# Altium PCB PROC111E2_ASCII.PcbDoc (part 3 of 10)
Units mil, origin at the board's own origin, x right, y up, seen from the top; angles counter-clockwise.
Board outline 7700 x 2300 mil, 6 copper layers (Top Layer, GND 1, SIG 1, SIG 2, GND 2, Bottom Layer), stack 78.711 mil thick; 767 components, 596 nets, 2755 pads, 1578 vias.
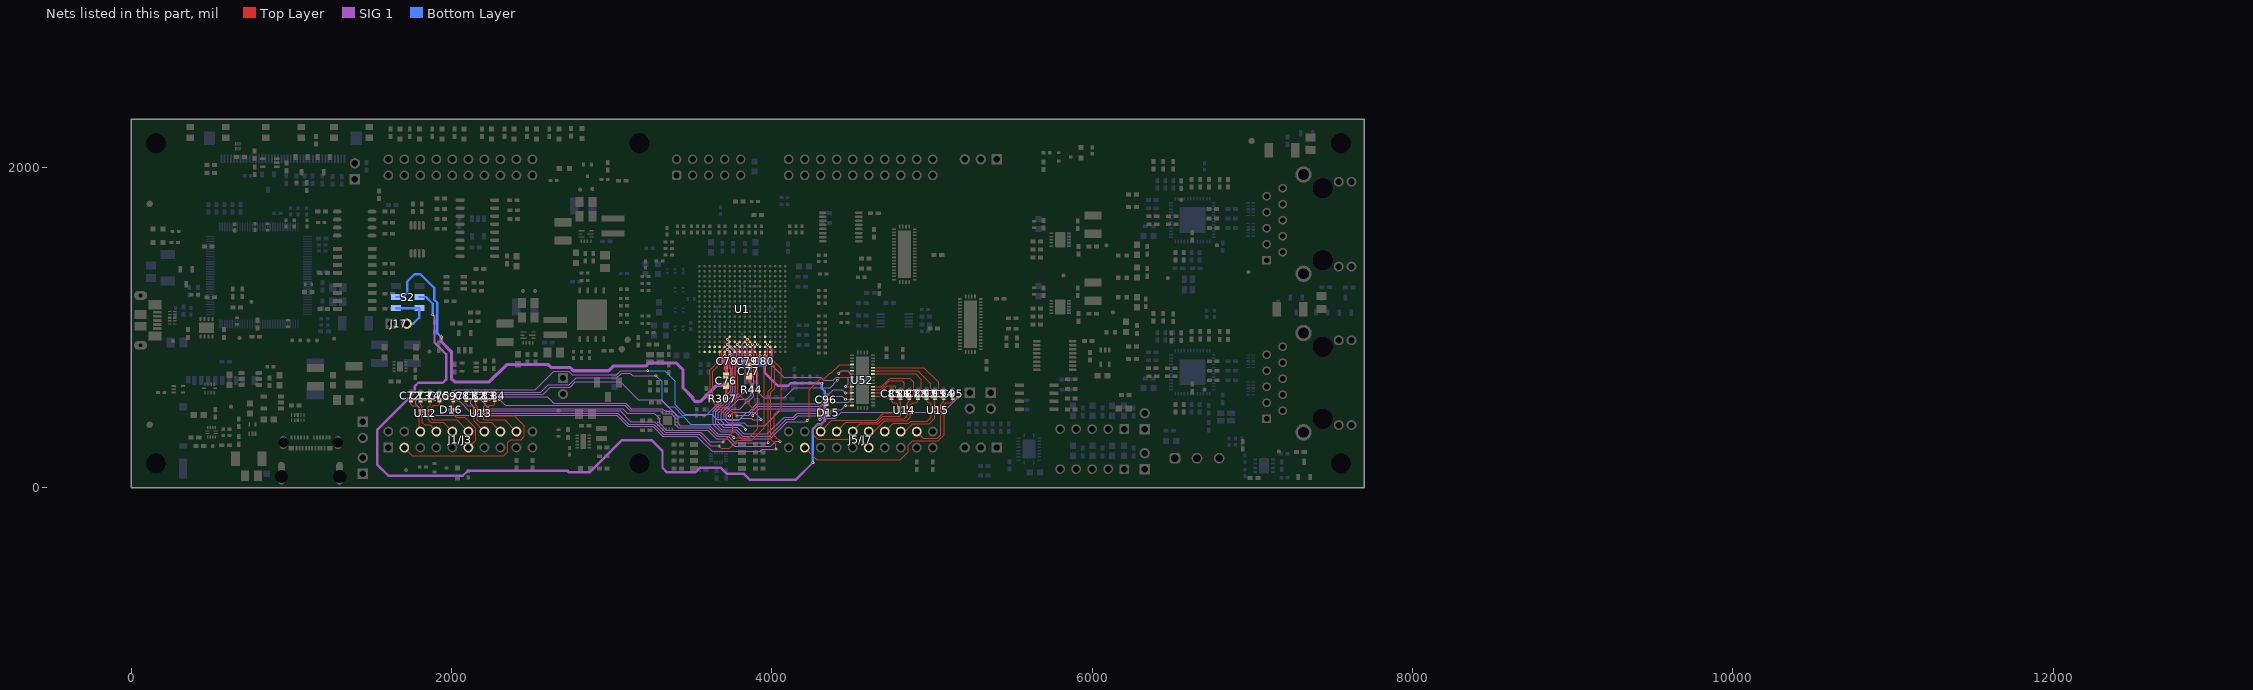
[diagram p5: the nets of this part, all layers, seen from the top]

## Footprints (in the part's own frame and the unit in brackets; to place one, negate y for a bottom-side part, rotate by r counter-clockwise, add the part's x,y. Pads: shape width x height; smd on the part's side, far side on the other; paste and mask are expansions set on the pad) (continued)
PDT0128A [mm] "Thin QFP, 128-Leads, Body 14x14mm, Pitch 0.4mm"
  oval 1.4x0.2 smd: 1(-7.7,6.2) 2(-7.7,5.8) 3(-7.7,5.4) 4(-7.7,5) 5(-7.7,4.6) 6(-7.7,4.2) 7(-7.7,3.8) 8(-7.7,3.4) 9(-7.7,3) 10(-7.7,2.6) 11(-7.7,2.2) 12(-7.7,1.8) 13(-7.7,1.4) 14(-7.7,1) 15(-7.7,0.6) 16(-7.7,0.2) 17(-7.7,-0.2) 18(-7.7,-0.6) 19(-7.7,-1) 20(-7.7,-1.4) 21(-7.7,-1.8) 22(-7.7,-2.2) 23(-7.7,-2.6) 24(-7.7,-3) 25(-7.7,-3.4) 26(-7.7,-3.8) 27(-7.7,-4.2) 28(-7.7,-4.6) 29(-7.7,-5) 30(-7.7,-5.4) 31(-7.7,-5.8) 32(-7.7,-6.2) 65(7.7,-6.2) 66(7.7,-5.8) 67(7.7,-5.4) 68(7.7,-5) 69(7.7,-4.6) 70(7.7,-4.2) 71(7.7,-3.8) 72(7.7,-3.4) 73(7.7,-3) 74(7.7,-2.6) 75(7.7,-2.2) 76(7.7,-1.8) 77(7.7,-1.4) 78(7.7,-1) 79(7.7,-0.6) 80(7.7,-0.2) 81(7.7,0.2) 82(7.7,0.6) 83(7.7,1) 84(7.7,1.4) 85(7.7,1.8) 86(7.7,2.2) 87(7.7,2.6) 88(7.7,3) 89(7.7,3.4) 90(7.7,3.8) 91(7.7,4.2) 92(7.7,4.6) 93(7.7,5) 94(7.7,5.4) 95(7.7,5.8) 96(7.7,6.2)
  oval 0.2x1.4 smd: 33(-6.2,-7.7) 34(-5.8,-7.7) 35(-5.4,-7.7) 36(-5,-7.7) 37(-4.6,-7.7) 38(-4.2,-7.7) 39(-3.8,-7.7) 40(-3.4,-7.7) 41(-3,-7.7) 42(-2.6,-7.7) 43(-2.2,-7.7) 44(-1.8,-7.7) 45(-1.4,-7.7) 46(-1,-7.7) 47(-0.6,-7.7) 48(-0.2,-7.7) 49(0.2,-7.7) 50(0.6,-7.7) 51(1,-7.7) 52(1.4,-7.7) 53(1.8,-7.7) 54(2.2,-7.7) 55(2.6,-7.7) 56(3,-7.7) 57(3.4,-7.7) 58(3.8,-7.7) 59(4.2,-7.7) 60(4.6,-7.7) 61(5,-7.7) 62(5.4,-7.7) 63(5.8,-7.7) 64(6.2,-7.7) 97(6.2,7.7) 98(5.8,7.7) 99(5.4,7.7) 100(5,7.7) 101(4.6,7.7) 102(4.2,7.7) 103(3.8,7.7) 104(3.4,7.7) 105(3,7.7) 106(2.6,7.7) 107(2.2,7.7) 108(1.8,7.7) 109(1.4,7.7) 110(1,7.7) 111(0.6,7.7) 112(0.2,7.7) 113(-0.2,7.7) 114(-0.6,7.7) 115(-1,7.7) 116(-1.4,7.7) 117(-1.8,7.7) 118(-2.2,7.7) 119(-2.6,7.7) 120(-3,7.7) 121(-3.4,7.7) 122(-3.8,7.7) 123(-4.2,7.7) 124(-4.6,7.7) 125(-5,7.7) 126(-5.4,7.7) 127(-5.8,7.7) 128(-6.2,7.7)
  silkscreen extent -7.7,-6.3 6.3,6.99
PW0016A_L [mm] "TSOP, 16-Leads, Body 5x4.4mm, Pitch 0.65mm, IPC High Density"
  oval 1.2x0.4 smd: 1(-2.85,2.275) 2(-2.85,1.625) 3(-2.85,0.975) 4(-2.85,0.325) 5(-2.85,-0.325) 6(-2.85,-0.975) 7(-2.85,-1.625) 8(-2.85,-2.275) 9(2.85,-2.275) 10(2.85,-1.625) 11(2.85,-0.975) 12(2.85,-0.325) 13(2.85,0.325) 14(2.85,0.975) 15(2.85,1.625) 16(2.85,2.275)
  silkscreen extent -2,-2.55 1.85,2.55
RGT0016A [mm] "QFN, 16-Leads, Body 3x3mm, Pitch 0.5mm, Thermal Pad 1.45x1.45mm, TI Recommended"
  rrect42% 0.6x0.24 smd: 1(-1.4,0.75) 2(-1.4,0.25) 3(-1.4,-0.25) 4(-1.4,-0.75) 9(1.4,-0.75) 10(1.4,-0.25) 11(1.4,0.25) 12(1.4,0.75)
  rrect42% 0.24x0.6 smd: 5(-0.75,-1.4) 6(-0.25,-1.4) 7(0.25,-1.4) 8(0.75,-1.4) 13(0.75,1.4) 14(0.25,1.4) 15(-0.25,1.4) 16(-0.75,1.4)
  rrect7% 1.34x1.34 on Top Paste: 17(0,0)
  rrect7% 1.45x1.45 smd paste-0.725: 17(0,0)
  silkscreen extent -1.72,-1.73 1.72,1.73
RGY0020A [mm] "QFN, 20-Leads, Body 4.5x3.5mm, Pitch 0.5mm, Thermal Pad 3.05x2.05mm, TI Recommended"
  oval 0.24x0.6 smd: 1(-0.75,2.15) 10(-0.75,-2.15) 11(0.75,-2.15) 20(0.75,2.15)
  oval 0.6x0.24 smd: 2(-1.65,1.75) 3(-1.65,1.25) 4(-1.65,0.75) 5(-1.65,0.25) 6(-1.65,-0.25) 7(-1.65,-0.75) 8(-1.65,-1.25) 9(-1.65,-1.75) 12(1.65,-1.75) 13(1.65,-1.25) 14(1.65,-0.75) 15(1.65,-0.25) 16(1.65,0.25) 17(1.65,0.75) 18(1.65,1.25) 19(1.65,1.75)
  rect 2.05x3.05 smd paste-1.025: 21(0,0)
  silkscreen extent -1.97,-2.47 1.97,2.48
RGZ0048B-MFG [mm]
  rrect42% 0.6x0.24 smd paste+0 mask+0: 1(-3.4,2.75) 2(-3.4,2.25) 3(-3.4,1.75) 4(-3.4,1.25) 5(-3.4,0.75) 6(-3.4,0.25) 7(-3.4,-0.25) 8(-3.4,-0.75) 9(-3.4,-1.25) 10(-3.4,-1.75) 11(-3.4,-2.25) 12(-3.4,-2.75) 25(3.4,-2.75) 26(3.4,-2.25) 27(3.4,-1.75) 28(3.4,-1.25) 29(3.4,-0.75) 30(3.4,-0.25) 31(3.4,0.25) 32(3.4,0.75) 33(3.4,1.25) 34(3.4,1.75) 35(3.4,2.25) 36(3.4,2.75)
  rrect42% 0.24x0.6 smd paste+0 mask+0: 13(-2.75,-3.4) 14(-2.25,-3.4) 15(-1.75,-3.4) 16(-1.25,-3.4) 17(-0.75,-3.4) 18(-0.25,-3.4) 19(0.25,-3.4) 20(0.75,-3.4) 21(1.25,-3.4) 22(1.75,-3.4) 23(2.25,-3.4) 24(2.75,-3.4) 37(2.75,3.4) 38(2.25,3.4) 39(1.75,3.4) 40(1.25,3.4) 41(0.75,3.4) 42(0.25,3.4) 43(-0.25,3.4) 44(-0.75,3.4) 45(-1.25,3.4) 46(-1.75,3.4) 47(-2.25,3.4) 48(-2.75,3.4)
  rrect2% 4.1x4.1 smd paste-1000 mask+0: 49(0,0)
  silkscreen extent -4.38,-3.57 3.57,3.57
RPU0010A-MFG [mm]
  rrect50% 0.65x0.2 smd paste+0 mask+0: 1(-0.875,0.25) 3(-0.875,-0.75) 5(0.875,-0.25)
  rrect50% 1x0.2 smd paste+0 mask+0: 2(-0.7,-0.25) 4(0.7,-0.75) 6(0.7,0.25)
  rrect40% 0.25x0.55 smd paste+0 mask+0: 7(0.75,0.925) 8(0.25,0.925) 9(-0.25,0.925) 10(-0.75,0.925)
  silkscreen extent -1.97,-1.5 1,1.6
RSE0010A [mm] "QFN, 10-Leads, Body 1.5x2mm, Pitch 0.5mm, TI Recommended"
  rect 0.55x0.2 smd: 1(-0.675,0.75) 2(-0.675,0.25) 3(-0.675,-0.25) 4(-0.675,-0.75) 6(0.675,-0.75) 7(0.675,-0.25) 8(0.675,0.25) 9(0.675,0.75)
  rect 0.3x0.6 smd: 5(0,-0.9) 10(0,0.9)
  silkscreen extent -1.07,-1.17 0.77,1.18
RSV0016A [mm] "QFN, 16-Leads, Body 1.8x2.6mm, Pitch 0.4mm, TI Recommended"
  rect 0.7x0.2 smd: 1(-0.75,0.6)
  rect 0.6x0.2 smd: 2(-0.8,0.2) 3(-0.8,-0.2) 4(-0.8,-0.6) 9(0.8,-0.6) 10(0.8,-0.2) 11(0.8,0.2) 12(0.8,0.6)
  rect 0.2x0.6 smd: 5(-0.6,-1.2) 6(-0.2,-1.2) 7(0.2,-1.2) 8(0.6,-1.2) 13(0.6,1.2) 14(0.2,1.2) 15(-0.2,1.2) 16(-0.6,1.2)
  silkscreen extent -1.08,-1.33 1.08,1.45
RUA0042A-MFG [mm]
  rrect40% 0.6x0.25 smd paste+0 mask+0: 1(-1.65,4) 2(-1.65,3.5) 3(-1.65,3) 4(-1.65,2.5) 5(-1.65,2) 6(-1.65,1.5) 7(-1.65,1) 8(-1.65,0.5) 9(-1.65,0) 10(-1.65,-0.5) 11(-1.65,-1) 12(-1.65,-1.5) 13(-1.65,-2) 14(-1.65,-2.5) 15(-1.65,-3) 16(-1.65,-3.5) 17(-1.65,-4) 22(1.65,-4) 23(1.65,-3.5) 24(1.65,-3) 25(1.65,-2.5) 26(1.65,-2) 27(1.65,-1.5) 28(1.65,-1) 29(1.65,-0.5) 30(1.65,0) 31(1.65,0.5) 32(1.65,1) 33(1.65,1.5) 34(1.65,2) 35(1.65,2.5) 36(1.65,3) 37(1.65,3.5) 38(1.65,4)
  rrect40% 0.25x0.6 smd paste+0 mask+0: 18(-0.75,-4.4) 19(-0.25,-4.4) 20(0.25,-4.4) 21(0.75,-4.4) 39(0.75,4.4) 40(0.25,4.4) 41(-0.25,4.4) 42(-0.75,4.4)
  rrect5% 2.05x7.55 smd paste-1000 mask+0: 43(0,0)
  silkscreen extent -2.65,-4.55 1.8,4.55
RWB0012A [mm] "QFN, 12-Leads, Body 1.6x1.6mm, Pitch 0.4mm"
  rrect57% 0.7x0.2 smd paste-0.1: 1(-0.65,0.2) 2(-0.65,-0.2) 7(0.65,-0.2) 8(0.65,0.2)
  rrect57% 0.2x0.5 smd: 3(-0.6,-0.75) 4(-0.2,-0.75) 5(0.2,-0.75) 6(0.6,-0.75) 9(0.6,0.75) 10(0.2,0.75) 11(-0.2,0.75) 12(-0.6,0.75)
  silkscreen extent -0.92,-0.91 0.92,0.91
SMB-Bi [mil] "Molded Diode, 2-Leads, Body 5.4x3.6mm, IPC Medium Density, based on OnSemi component dimensions"
  rect 85x107.99 smd: 1(-87.01,0) 2(87.01,0)
  silkscreen extent -125,-79 125,79
SOIC-8 [mm] "duplicate of SO-8.  SOIC, 8-Leads, Body 5.0x4.0mm (max), Pitch 1.27mm, IPC Medium Density"
  rrect17% 1.45x0.6 smd: 1(-2.725,1.905) 2(-2.725,0.635) 3(-2.725,-0.635) 4(-2.725,-1.905) 5(2.725,-1.905) 6(2.725,-0.635) 7(2.725,0.635) 8(2.725,1.905)
  silkscreen extent -3.5,-2.5 0.9,2.5
SOT-23 [mm] "SOT23, 3-Leads, Body 2.9x1.3mm, Pitch 0.95mm, Lead Span 2.5mm, IPC Medium Density"
  rrect50% 1x0.6 smd: 1(-1.2,0.95) 2(-1.2,-0.95) 3(1.2,0)
  silkscreen extent -1.63,-1.5 0.7,1.5
SOT-323 [mm] "Diodes Inc recommended land pattern.  2016-02-24"
  rrect21% 0.6x0.47 smd: 1(-0.95,0.65) 2(-0.95,-0.65) 3(0.95,0)
  silkscreen extent -1.14,-1.22 0.77,1.22
Sullins_PBC02SAAN [mm] "Sullins 100mil, 1x2, 230 mil above insulator"
  rect 1.65x1.65 hole 1.016: 1(0,1.27)
  round 1.65 hole 1.016: 2(0,-1.27)
  silkscreen extent -1.37,-2.54 1.27,3.1
Sullins_PxC05SAAN [mm] "Header, 2.54mm, 5x1, TH"
  rect 1.55x1.55 hole 1.016: 1(-5.08,0)
  round 1.55 hole 1.016: 2(-2.54,0) 3(0,0) 4(2.54,0) 5(5.08,0)
  silkscreen extent -6.35,-1.75 6.35,1.27
Sullins_xxPC005DAAN-RC [mm] "Header, 2.54mm, 5x2, TH"
  rrect50% 1.5x1.5 hole 1: 1(-1.27,5.08)
  round 1.5 hole 1: 2(1.27,5.08) 3(-1.27,2.54) 4(1.27,2.54) 5(-1.27,0) 6(1.27,0) 7(-1.27,-2.54) 8(1.27,-2.54) 9(-1.27,-5.08) 10(1.27,-5.08)
SW_CAS-120TA [mm] "COPAL ELECTRONICS"
  rect 1.6x1 smd: 1(-1.15,1.75) 2(1.15,0) 3(-1.15,-1.75)
  silkscreen extent -2,-2.85 1.4,2.93
SW_CAS-D20TA [mm] "SMD, 6-Leads, Body 5.4x3.9mm, Pitch 1.75mm"
  rect 1.6x1 smd: 1(-1.85,1.75) 2(-1.85,0) 3(-1.85,-1.75) 4(1.85,1.75) 5(1.85,0) 6(1.85,-1.75)
  silkscreen extent -1.95,-2.7 1.95,2.9
TI_Stacked_Overlay_Small [mil]
TP_25MIL-SMT [mil]
  round 25 smd mask+0: 1(0,0)
TP_SM_1MM [mm] "1mm Test Point, SMT"
  round 1 smd paste-0.5: 1(0,0)
WE-MAPI_4020 [mm] "SMD, 2-Leads, Body 4.1x4.1mm"
  rect 0.98x3.7 smd: 1(-1.185,0) 2(1.185,0)
  silkscreen extent -2.15,-2.15 2.15,2.15
WEEE_Minimum [mil] "WEEElie bin"
  silkscreen extent 22,-71 54,74
WL-SMCW_GREEN [mm] "WURTH"
  rect 0.8x0.8 smd: 1(-0.8,0) 2(0.8,0)
  silkscreen extent -1.9,-0.8 1.2,0.8
WL-SMCW_RED [mm] "WURTH"
  rect 0.8x0.8 smd: 1(-0.8,0) 2(0.8,0)
  silkscreen extent -1.9,-0.8 1.2,0.8
Wurth_60900213421 [mil] "Shunt, 2.54mm, Black"
  round 1 on Mech3: 0(0,0)
"ZCZ (S-PBGA-N324)" [mm] "0.8mm pitch, 15x15mm, Plastic Ball Grid Array"
  round 0.4 smd: A1(0,0) A2(0.8,0) A3(1.6,0) A4(2.4,0) A5(3.2,0) A6(4,0) A7(4.8,0) A8(5.6,0) A9(6.4,0) A10(7.2,0) A11(8,0) A12(8.8,0) A13(9.6,0) A14(10.4,0) A15(11.2,0) A16(12,0) A17(12.8,0) A18(13.6,0) B1(0,-0.8) B2(0.8,-0.8) B3(1.6,-0.8) B4(2.4,-0.8) B5(3.2,-0.8) B6(4,-0.8) B7(4.8,-0.8) B8(5.6,-0.8) B9(6.4,-0.8) B10(7.2,-0.8) B11(8,-0.8) B12(8.8,-0.8) B13(9.6,-0.8) B14(10.4,-0.8) B15(11.2,-0.8) B16(12,-0.8) B17(12.8,-0.8) B18(13.6,-0.8) C1(0,-1.6) C2(0.8,-1.6) C3(1.6,-1.6) C4(2.4,-1.6) C5(3.2,-1.6) C6(4,-1.6) C7(4.8,-1.6) C8(5.6,-1.6) C9(6.4,-1.6) C10(7.2,-1.6) C11(8,-1.6) C12(8.8,-1.6) C13(9.6,-1.6) C14(10.4,-1.6) C15(11.2,-1.6) C16(12,-1.6) C17(12.8,-1.6) C18(13.6,-1.6) D1(0,-2.4) D2(0.8,-2.4) D3(1.6,-2.4) D4(2.4,-2.4) D5(3.2,-2.4) D6(4,-2.4) D7(4.8,-2.4) D8(5.6,-2.4) D9(6.4,-2.4) D10(7.2,-2.4) D11(8,-2.4) D12(8.8,-2.4) D13(9.6,-2.4) D14(10.4,-2.4) D15(11.2,-2.4) D16(12,-2.4) D17(12.8,-2.4) D18(13.6,-2.4) E1(0,-3.2) E2(0.8,-3.2) E3(1.6,-3.2) E4(2.4,-3.2) E5(3.2,-3.2) E6(4,-3.2) E7(4.8,-3.2) E8(5.6,-3.2) E9(6.4,-3.2) E10(7.2,-3.2) E11(8,-3.2) E12(8.8,-3.2) E13(9.6,-3.2) E14(10.4,-3.2) E15(11.2,-3.2) E16(12,-3.2) E17(12.8,-3.2) E18(13.6,-3.2) F1(0,-4) F2(0.8,-4) F3(1.6,-4) F4(2.4,-4) F5(3.2,-4) F6(4,-4) F7(4.8,-4) F8(5.6,-4) F9(6.4,-4) F10(7.2,-4) F11(8,-4) F12(8.8,-4) F13(9.6,-4) F14(10.4,-4) F15(11.2,-4) F16(12,-4) F17(12.8,-4) F18(13.6,-4) G1(0,-4.8) G2(0.8,-4.8) G3(1.6,-4.8) G4(2.4,-4.8) G5(3.2,-4.8) G6(4,-4.8) G7(4.8,-4.8) G8(5.6,-4.8) G9(6.4,-4.8) G10(7.2,-4.8) G11(8,-4.8) G12(8.8,-4.8) G13(9.6,-4.8) G14(10.4,-4.8) G15(11.2,-4.8) G16(12,-4.8) G17(12.8,-4.8) G18(13.6,-4.8) H1(0,-5.6) H2(0.8,-5.6) H3(1.6,-5.6) H4(2.4,-5.6) H5(3.2,-5.6) H6(4,-5.6) H7(4.8,-5.6) H8(5.6,-5.6) H9(6.4,-5.6) H10(7.2,-5.6) H11(8,-5.6) H12(8.8,-5.6) H13(9.6,-5.6) H14(10.4,-5.6) H15(11.2,-5.6) H16(12,-5.6) H17(12.8,-5.6) H18(13.6,-5.6) J1(0,-6.4) J2(0.8,-6.4) J3(1.6,-6.4) J4(2.4,-6.4) J5(3.2,-6.4) J6(4,-6.4) J7(4.8,-6.4) J8(5.6,-6.4) J9(6.4,-6.4) J10(7.2,-6.4) J11(8,-6.4) J12(8.8,-6.4) J13(9.6,-6.4) J14(10.4,-6.4) J15(11.2,-6.4) J16(12,-6.4) J17(12.8,-6.4) J18(13.6,-6.4) K1(0,-7.2) K2(0.8,-7.2) K3(1.6,-7.2) K4(2.4,-7.2) K5(3.2,-7.2) K6(4,-7.2) K7(4.8,-7.2) K8(5.6,-7.2) K9(6.4,-7.2) K10(7.2,-7.2) K11(8,-7.2) K12(8.8,-7.2) K13(9.6,-7.2) K14(10.4,-7.2) K15(11.2,-7.2) K16(12,-7.2) K17(12.8,-7.2) K18(13.6,-7.2) L1(0,-8) L2(0.8,-8) L3(1.6,-8) L4(2.4,-8) L5(3.2,-8) L6(4,-8) L7(4.8,-8) L8(5.6,-8) L9(6.4,-8) L10(7.2,-8) L11(8,-8) L12(8.8,-8) L13(9.6,-8) L14(10.4,-8) L15(11.2,-8) L16(12,-8) L17(12.8,-8) L18(13.6,-8) M1(0,-8.8) M2(0.8,-8.8) M3(1.6,-8.8) M4(2.4,-8.8) M5(3.2,-8.8) M6(4,-8.8) M7(4.8,-8.8) M8(5.6,-8.8) M9(6.4,-8.8) M10(7.2,-8.8) M11(8,-8.8) M12(8.8,-8.8) M13(9.6,-8.8) M14(10.4,-8.8) M15(11.2,-8.8) M16(12,-8.8) M17(12.8,-8.8) M18(13.6,-8.8) N1(0,-9.6) N2(0.8,-9.6) N3(1.6,-9.6) N4(2.4,-9.6) N5(3.2,-9.6) N6(4,-9.6) N7(4.8,-9.6) N8(5.6,-9.6) N9(6.4,-9.6) N10(7.2,-9.6) N11(8,-9.6) N12(8.8,-9.6) N13(9.6,-9.6) N14(10.4,-9.6) N15(11.2,-9.6) N16(12,-9.6) N17(12.8,-9.6) N18(13.6,-9.6) P1(0,-10.4) P2(0.8,-10.4) P3(1.6,-10.4) P4(2.4,-10.4) P5(3.2,-10.4) P6(4,-10.4) P7(4.8,-10.4) P8(5.6,-10.4) P9(6.4,-10.4) P10(7.2,-10.4) P11(8,-10.4) P12(8.8,-10.4) P13(9.6,-10.4) P14(10.4,-10.4) P15(11.2,-10.4) P16(12,-10.4) P17(12.8,-10.4) P18(13.6,-10.4) R1(0,-11.2) R2(0.8,-11.2) R3(1.6,-11.2) R4(2.4,-11.2) R5(3.2,-11.2) R6(4,-11.2) R7(4.8,-11.2) R8(5.6,-11.2) R9(6.4,-11.2) R10(7.2,-11.2) R11(8,-11.2) R12(8.8,-11.2) R13(9.6,-11.2) R14(10.4,-11.2) R15(11.2,-11.2) R16(12,-11.2) R17(12.8,-11.2) R18(13.6,-11.2) T1(0,-12) T2(0.8,-12) T3(1.6,-12) T4(2.4,-12) T5(3.2,-12) T6(4,-12) T7(4.8,-12) T8(5.6,-12) T9(6.4,-12) T10(7.2,-12) T11(8,-12) T12(8.8,-12) T13(9.6,-12) T14(10.4,-12) T15(11.2,-12) T16(12,-12) T17(12.8,-12) T18(13.6,-12) U1(0,-12.8) U2(0.8,-12.8) U3(1.6,-12.8) U4(2.4,-12.8) U5(3.2,-12.8) U6(4,-12.8) U7(4.8,-12.8) U8(5.6,-12.8) U9(6.4,-12.8) U10(7.2,-12.8) U11(8,-12.8) U12(8.8,-12.8) U13(9.6,-12.8) U14(10.4,-12.8) U15(11.2,-12.8) U16(12,-12.8) U17(12.8,-12.8) U18(13.6,-12.8) V1(0,-13.6) V2(0.8,-13.6) V3(1.6,-13.6) V4(2.4,-13.6) V5(3.2,-13.6) V6(4,-13.6) V7(4.8,-13.6) V8(5.6,-13.6) V9(6.4,-13.6) V10(7.2,-13.6) V11(8,-13.6) V12(8.8,-13.6) V13(9.6,-13.6) V14(10.4,-13.6) V15(11.2,-13.6) V16(12,-13.6) V17(12.8,-13.6) V18(13.6,-13.6)
  silkscreen extent -0.8,-14.4 14.4,0.8

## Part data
C1 C2 C3 C4 C5 C6 C14 C23 C25 C52 C53 C68 C236: library part CMP-0007057-4, "CAP, CERM, 3.3 uF, 10 V, +/- 10%, X7S, 0603"
C7 C8 C9 C10 C11 C12 C13 C15 C16 C17 C18 C24 C26 C27 C28 C34 C35 C36 C37 C38 C48 C69 C72 C73 C74 C75 C78 C79 C80 C81 C82 C83 C84 C85 C86 C87 C88 C90 C91 C92 C93 C94 C95 C96 C97 C98 C117 C119 C121 C125 C127 C131 C133 C165 C176 C194 C196 C198 C202 C204 C208 C210 C237: library part CMP-0006623-2, "CAP, CERM, 0.1 uF, 6.3 V, +/- 10%, X7R, 0402"
C19 C20 C21 C22 C29 C30 C31 C32 C39 C40 C41 C42 C44 C45 C46 C47: library part CMP-0093721-1, "Chip Multilayer Ceramic Capacitors for General Purpose, 0201, 1.0uF, X6S, 22%, 20%, 6.3V"
C33 C76 C77 C89: library part CMP-0007498-4, "CAP, CERM, 4.7 uF, 10 V, +/- 20%, X7R, 0603"
C43 C57 C60 C61 C62 C64 C65 C66 C70 C71 C99 C100 C111 C134 C136 C137 C138 C139 C140 C141 C142 C145 C147 C150 C151 C154 C155 C163 C174 C181 C182 C183 C184 C186 C188 C223 C225 C226 C233 C238 C239 C240 C241 C242 C243 C244 C245 C246: library part CMP-0006659-2, "CAP, CERM, 0.1 uF, 25 V, +/- 10%, X7R, 0402"
C49 C50 C51 C54 C55 C56: library part CMP-0064970-1, "CAP, CERM, 0.1 uF, 16 V,+/- 10%, X7R, 0201"
C58 C59 C112 C113 C189 C190: library part CMP-0006375-2, "CAP, CERM, 12 pF, 25 V, +/- 5%, C0G/NP0, 0402"
C63 C135 C149 C152: library part CMP-0006658-2, "CAP, CERM, 0.01 uF, 25 V, +/- 10%, X7R, 0402"
C67 C161 C172: library part CMP-0064936-4, "CAP, CERM, 4.7 uF, 16 V,+/- 10%, X7R, 0603"
C101 C106 C108 C110 C248 C249: library part CMP-0007135-4, "CAP, CERM, 0.1 uF, 16 V, +/- 10%, X7R, AEC-Q200 Grade 1, 0603"
C102 C104 C105 C107 C164 C167 C168 C175 C179 C180: library part CMP-0081639-1, "CAP, CERM, 10 µF, 35 V,+/- 10%, X7R, 1210"
C103: library part CMP-0007470-5, "CAP, CERM, 0.1 uF, 100 V, +/- 10%, X7R, 0603"
C109: library part CMP-0006638-1, "CAP, CERM, 1000 pF, 16 V, +/- 10%, X7R, 0402"
C114 C122 C128 C191 C199 C205: library part CMP-0007497-5, "CAP, CERM, 10 uF, 10 V, +/- 20%, X7R, 0603"
C115 C123 C129 C192 C200 C206: library part CMP-0006622-2, "CAP, CERM, 0.01 uF, 6.3 V, +/- 10%, X7R, 0402"
C116 C118 C120 C124 C126 C130 C132 C193 C195 C197 C201 C203 C207 C209: library part CMP-0006624-2, "CAP, CERM, 1 uF, 6.3 V, +/- 20%, X7R, 0402"
C143 C144: library part CMP-0087060-3, "Cap Ceramic 8pF 50V C0G 0.5pF SMD 0402 125C Paper T/R"
C146 C148 C156 C162 C173 C187 C232: library part CMP-0006349-2, "CAP, CERM, 1 uF, 10 V, +/- 10%, X7S, AEC-Q200 Grade 1, 0402"
C153 C231: library part CMP-0006526-2, "CAP, CERM, 2.2 uF, 16 V, +/- 10%, X6S, 0402"
C157 C158 C169 C170 C185: library part CMP-0008377-2, "CAP, CERM, 22 uF, 10 V, +/- 20%, X7R, 0805"
C159 C171: library part CMP-0009221-2, "CAP, CERM, 47 uF, 10 V, +/- 20%, X7R, 1210"
C160 C177: library part CMP-0007424-4, "CAP, CERM, 0.47 uF, 25 V, +/- 10%, X7R, 0603"
C166 C178: library part CMP-0006706-2, "CAP, CERM, 2700 pF, 100 V, +/- 10%, X7R, 0402"
C211 C212 C213 C224: library part CMP-0007144-4, "CAP, CERM, 0.1 uF, 50 V, +/- 10%, X7R, 0603"
C214 C216 C217 C219 C220 C221: library part CMP-0086079-1, "CAP, CERM, 1000 pF, 50 V,+/- 5%, C0G/NP0, AEC-Q200 Grade 1, 0603"
C215 C218: library part CMP-0007171-4, "CAP, CERM, 100 pF, 50 V, +/- 5%, C0G/NP0, 0603"
C222: library part CMP-0006361-2, "CAP, CERM, 4700 pF, 50 V, +/- 10%, X7R, AEC-Q200 Grade 1, 0402"
C227: library part CMP-0008378-2, "CAP, CERM, 10 uF, 25 V, +/- 10%, X7R, 0805"
C228: library part CMP-0006420-2, "CAP, CERM, 15 pF, 50 V, +/- 5%, C0G/NP0, 0402"
C229 C230 C234 C235 C247: library part CMP-0009436-2, "CAP, CERM, 1000 pF, 2000 V, +/- 10%, X7R, 1808"
D1: library part CMP-0005599-2, "Diode, TVS, Bi, 6.5 V, SMB"
D2 D3 D4 D5 D6 D7 D8 D9 D10 D11 D12 D13 D14: library part CMP-0002894-2, "LED, Green, SMD"
D15 D16: library part CMP-0073602-3, "1-Channel ESD Protection Diode for USB Type-C and Thunderbolt 3, DPY0002A (X1SON-2)"
DS1 DS2 DS3: library part CMP-0002947-3, "LED, Red, SMD"
FB1 FB2 FB3 FB4 FB5 FB6: library part CMP-0089199-1, "120 Ohms @ 100MHz 1  Ferrite Bead 0603 (1608 Metric) 2A 40mOhm"
FID1 FID2 FID3: library part CMP-0077181-1, "Fiducial mark.  There is nothing to buy or mount."
J1 J9 J10 J13 J14 J15 J16 J17 J18: library part CMP-0054566-1, "Header, 100mil, 2x1, Gold, TH"
J1/J3: library part CMP-0003837-4, "Receptacle, 2.54mm, 10x2, Tin, TH"
J2: library part CMP-0080007-1, "Conncetor, micro SD, 8+2 Pos, R/A, SMT"
J2/J4: library part CMP-0078266-4, "Receptacle, 2.54mm, 10x2, Tin, TH"
J5: library part CMP-0093552-1, "USB-C (USB TYPE-C) USB 3.2 Gen 2 (USB 3.1 Gen 2, Superspeed + (USB 3.1)) Receptacle Connector 24 Position Surface Mount, Right Angle; Through Hole"
J5/J7: library part CMP-0081070-3, "Receptacle, 2.54mm, 10x2, Tin, TH"
J6: library part CMP-0093156-1
J6/J8: library part CMP-0081071-3, "Receptacle, 2.54mm, 10x2, Tin, TH"
J7 J8: library part CMP-0093483-1, "RJ45 Connector with 1000 Base-TX Inetgrated Magnetic"
J11 J12: library part CMP-0002334-1, "Header, 100mil, 3x1, Gold, TH"
J23: library part CMP-0080722-2, "Header, 2.54mm, 5x2, Gold, TH"
J24 J25: library part CMP-0054597-1, "Header, 2.54mm, 5x1, Tin, TH"
J33: library part CMP-0075352-1, "Terminal Block, 3.5mm, 3x1, Tin, R/A, TH"
J34: library part CMP-0055311-1, "Receptacle, USB 2.0, Micro B, 5 Position, R/A, SMT"
L1: library part CMP-0003364-1, "Ferrite Bead, 30 ohm @ 100 MHz, 4 A, 0805"
L2 L3: library part CMP-0064169-1, "Inductor, Shielded, 2.2 uH, 4.7 A, 0.029 ohm, SMD"
L4: library part CMP-0078538-1, "10µH Semi-Shielded Wirewound Inductor 580mA 816 mOhm Max Nonstandard"
LBL1: library part CMP-0003625-1, "Thermal Transfer Printable Labels, 0.650\" W x 0.200\" H - 10,000 per roll"
Logo1: library part CMP-0074844-1
Logo2: library part CMP-0074838-1, "Texas Instrument Corporate Signature"
Logo3: library part CMP-0074847-1, "FCC_disclaimer"
Logo4: library part CMP-0074769-1
Q1 Q2 Q3: library part CMP-0078819-2, "MOSFET, P-CH, -12 V, -4.3 A, SOT-23"
Q4 Q5 Q6 Q7 Q8 Q9: library part CMP-0000947-2, "MOSFET, N-CH, 100 V, 0.17 A, SOT-23"
Q10: library part CMP-0000010-3, "MOSFET, P-CH, -20 V, -0.39 A, SOT-323"
Q11 Q13: library part CMP-0000948-2, "MOSFET, N-CH, 100 V, 0.17 A, SOT-323"
R1 R6 R8 R10 R11 R14 R15 R16 R17 R20 R42 R43 R92 R93 R98 R146 R147 R155 R156 R173 R174 R177 R178 R179 R181 R182 R183 R184 R185 R186 R187 R188 R194 R258 R268 R269 R270 R271 R274 R275 R276 R287 R288 R291 R292 R295 R296 R298 R299 R305 R306 R316 R318 R319 R320 R321 R322 R323: library part CMP-0026658-1, "RES, 10.0 k, 1%, 0.1 W, 0402"
R2: library part CMP-0026240-2, "RES, 2.67 k, 1%, 0.063 W, AEC-Q200 Grade 0, 0402"
R3 R4 R5 R7 R9 R12 R13 R18 R26 R27 R28 R29 R30 R33 R34 R35 R36 R37 R38 R44 R45 R46 R47 R48 R49 R50 R51 R52 R53 R54 R57 R58 R59 R60 R61 R62 R65 R66 R67 R68 R69 R70 R71 R72 R75 R76 R77 R78 R79 R80 R81 R82 R83 R84 R85 R86 R87 R88 R89 R90 R99 R100 R101 R102 R103 R104 R105 R106 R117 R118 R119 R129 R130 R131 R149 R150 R157 R158 R164 R165 R166 R167 R168 R169 R170 R171 R172 R180 R193 R196 R197 R198 R199 R200 R201 R212 R213 R214 R225 R227 R229 R231 R233 R235 R245 R248 R249 R280 R281 R282 R283 R284 R285 R286 R297 R307: library part CMP-0026992-3, "RES, 0, 5%, 0.1 W, AEC-Q200 Grade 0, 0402"
R19: library part CMP-0026703-1, "RES, 49.9, 1%, 0.1 W, AEC-Q200 Grade 0, 0402"
R21 R22 R23 R24 R25 R96 R97 R256 R278 R289 R290 R293 R294 R300 R304: library part CMP-0078193-1, "RES, 1.0 k, 5%, 0.1 W, AEC-Q200 Grade 0, 0402"
R31: library part CMP-0026395-2, "RES, 47.5 k, 1%, 0.063 W, AEC-Q200 Grade 0, 0402"
R32 R253 R254 R255: library part CMP-0021522-3, "RES, 1.00 M, 1%, 0.125 W, AEC-Q200 Grade 0, 0805"
R39 R40 R41 R143 R244 R250: library part CMP-0025958-3, "RES, 10.0 k, 1%, 0.063 W, AEC-Q200 Grade 0, 0402"
R55 R56 R63 R64 R73 R74 R95 R175 R176 R189 R190 R191 R192: library part CMP-0026938-5, "RES, 4.7 k, 5%, 0.063 W, AEC-Q200 Grade 0, 0402"
R91: library part CMP-0026873-2, "RES, 200 k, 5%, 0.063 W, AEC-Q200 Grade 0, 0402"
R94: library part CMP-0026603-2, "RES, 909 k, 1%, 0.063 W, AEC-Q200 Grade 0, 0402"
R107 R202: library part CMP-0082348-1, "RES, 11.5 k, 1%, 0.1 W, AEC-Q200 Grade 0, 0402"
R108 R109 R110 R111 R112 R113 R114 R115 R116 R120 R121 R122 R123 R124 R125 R126 R127 R128 R153 R203 R204 R205 R206 R207 R208 R209 R210 R211 R215 R216 R217 R218 R219 R220 R221 R222 R223: library part CMP-0026237-2, "RES, 2.49 k, 1%, 0.063 W, AEC-Q200 Grade 0, 0402"
R132: library part CMP-0026993-2, "RES, 100, 5%, 0.1 W, AEC-Q200 Grade 0, 0402"
R133 R134 R135 R324 R325 R326 R327 R328 R329 R330 R331 R332 R333 R334 R335: library part CMP-0026299-2, "RES, 33.2, 1%, 0.063 W, AEC-Q200 Grade 0, 0402"
R136 R137: library part CMP-0078210-2, "RES, 330 k, 1%, 0.063 W, AEC-Q200 Grade 0, 0402"
R138 R139 R140 R141 R144 R261 R308 R309 R310 R311 R312: library part CMP-0026071-3, "RES, 1.00 k, 1%, 0.063 W, AEC-Q200 Grade 0, 0402"
R142: library part CMP-0026404-2, "RES, 49.9, 1%, 0.063 W, AEC-Q200 Grade 0, 0402"
R145: library part CMP-0026413-2, "RES, 4.87 k, 1%, 0.063 W, AEC-Q200 Grade 0, 0402"
R148 R160: library part CMP-0021602-3, "RES, 18.2 k, 1%, 0.125 W, AEC-Q200 Grade 0, 0805"
R151: library part CMP-0026336-2, "RES, 3.57 k, 1%, 0.063 W, AEC-Q200 Grade 0, 0402"
R152: library part CMP-0026093-3, "RES, 1.69 k, 1%, 0.063 W, AEC-Q200 Grade 0, 0402"
R154 R161 R163: library part CMP-0026414-2, "RES, 4.99 k, 1%, 0.063 W, AEC-Q200 Grade 0, 0402"
R159: library part CMP-0026097-2, "RES, 1.87 k, 1%, 0.063 W, AEC-Q200 Grade 0, 0402"
R162: library part CMP-0026028-3, "RES, 15.4 k, 1%, 0.063 W, AEC-Q200 Grade 0, 0402"
R195: library part CMP-0026659-2, "RES, 100 k, 1%, 0.1 W, 0402"
R224 R226 R228 R230 R232 R234: library part CMP-0026878-3, "RES, 220, 5%, 0.063 W, AEC-Q200 Grade 0, 0402"
R236 R237 R238 R239 R240 R241 R242 R243: library part CMP-0026702-1, "RES, 49.9 k, 1%, 0.1 W, AEC-Q200 Grade 0, 0402"
R246 R247: library part CMP-0026491-2, "RES, 61.9, 1%, 0.063 W, AEC-Q200 Grade 0, 0402"
R251: library part CMP-0026437-2, "RES, 51.1 k, 1%, 0.063 W, AEC-Q200 Grade 0, 0402"
R252: library part CMP-0078244-2, "RES, 30.0 k, 1%, 0.063 W, AEC-Q200 Grade 0, 0402"
R257: library part CMP-0026704-1, "RES, 510, 1%, 0.1 W, 0402"
R259 R260 R265 R302 R314: library part CMP-0078194-1, "RES, 360, 5%, 0.1 W, AEC-Q200 Grade 0, 0402"
R262 R263 R264 R266 R267 R273 R277 R279: library part CMP-0026680-1, "RES, 220, 1%, 0.1 W, AEC-Q200 Grade 0, 0402"
R272 R303 R317: library part CMP-0078212-1, "RES, 510, 5%, 0.1 W, AEC-Q200 Grade 0, 0402"
R313 R315: library part CMP-0025998-3, "RES, 130, 1%, 0.063 W, AEC-Q200 Grade 0, 0402"
S1: library part CMP-0002139-2, "Switch, Slide, SPDT  100mA, SMT"
S2: library part CMP-0002233-1, "Switch, Dual SPDT,  2 Pos, 0.1A, 6VDC, SMD"
SH-J1 SH-J2 SH-J3 SH-J4 SH-J5 SH-J6 SH-J7: library part CMP-0003761-2, "Shunt, 2.54mm, Gold, Black"
SW1: library part CMP-0093176-1, "Dip Switch SPST 4 Position Surface Mount Slide (Standard) Actuator 25mA 24VDC"
SW2 SW3 SW4: library part CMP-0093456-1, "Tactile Switch SPST-NO Side Actuated Surface Mount, Right Angle"
TP1 TP2: library part CMP-0003825-1, "1mm Test Point, SMT"
TP3 TP4 TP5 TP6 TP7 TP8 TP9 TP10 TP11 TP12 TP13 TP14 TP15 TP16 TP17 TP18 TP19 TP20 TP21 TP22 TP23 TP24 TP25 TP26 TP27 TP28 TP29 TP30: library part CMP-0078143-3, "TEST POINT.  No entry in BOM."
U1: "Sitara AM263x MCU (Pinlist Revision 0.96, Pinmux 0.98)"
U2: library part CMP-0051219-1, "Single 3-Input Positive-AND Gate, DBV0006A, LARGE T&R"
U3: library part CMP-0043157-2, "Low-Voltage 8-Bit I2C and SMBus I/O Expander, 1.65 to 5.5 V, -40 to 85 degC, 16-pin QFN (RGT), Green (RoHS & no Sb/Br)"
U4: library part CMP-0066450-2, "4-Bit Dual-Supply Bus Transceiver with Configurable Voltage-Level Shifting and 3-State Outputs, RSV0016A (UQFN-16)"
U5 U9 U47: library part CMP-0051588-2, "Single 2-Input Positive-AND Gate, DBV0005A, LARGE T&R"
U6: library part CMP-0051704-3, "Single Schmitt-Trigger Buffer, DCK0005A, LARGE T&R"
U7: library part CMP-0093537-1, "FLASH - NOR Memory IC 128Mb (16M x 8) SPI - Quad I/O 133 MHz 8-WSON (6x8)"
U8: library part CMP-0081995-1, "5.5V, 2A, 52mO Automotive High-Side Load Switch with Adjustable Rise Time & Quick Output Discharge, DBV0006A (SOT-23-6)"
U10: library part CMP-0043096-2, "Low-Capacitance + / - 15 kV ESD-Protection Array for High-Speed Data Interfaces, 2 Channels, -40 to +85 degC, 5-pin SOT (DRL), Green (RoHS & no Sb/Br)"
U11: library part CMP-0043123-1, "Low-Capacitance + / - 15 kV ESD Protection Array for High-Speed Data Interfaces, 6 Channels, -40 to +85 degC, 10-pin UQFN (RSE), Green (RoHS & no Sb/Br)"
U12 U13 U14 U15 U20 U44: library part CMP-0073612-3, "4-Channel ESD Protection Diode for USB Type-C and HDMI 2.0, DQA0010A (USON-10)"
U16: library part CMP-0005327-2, "1024-Kb I2C CMOS Serial EEPROM, SOIC-8"
U17: library part CMP-0067419-2, "2-Channel, 2:1 Analog Switch with Low On-State Resistance (1ohm) and Powered Off Protection, DGS0010A (VSSOP-10)"
U18: library part CMP-0073635-2, "USB Type-C Configuration Channel Logic and Port Control, RWB0012A (X2QFN-12)"
U19: library part CMP-0073678-3, "5.5V, 4A, 16mO Automotive Load Switch With Adjustable Rise Time and Optional Quick Output Discharge, DSG0008B (WSON-8)"
U21: library part CMP-0051530-2, "Single 2-Input Positive-NOR Gate, DRL0005A, LARGE T&R"
U22 U37: library part CMP-0091377-1, "1/1 Transceiver Ethernet 48-VQFN (7x7)"
U23 U50 U52: library part CMP-0093539-2, "IC MUX/DEMUX DDR3 1:2 42WQFN"
U24: library part CMP-0029856-2, "Tiva C Series Microcontroller, 1024 KB Flash, 256 KB SRAM, 12 Bit, 20 Channels, -40 to 105 degC, 128-Pin TQFP (PDT), Green (RoHS & no Sb/Br), Tray"
U25: library part CMP-0029369-1, "25 Mbps Dual Channels, 2 / 0, Digital Isolator, 3.3 V / 5 V, -40 to +125 degC, 8-pin SOIC (D), Green (RoHS & no Sb/Br)"
U26 U27: library part CMP-0076059-2, "High Speed, Robust EMC Dual-Channel Digital Isolator, D0008B (SOIC-8)"
U28: library part CMP-0033001-1, "Precision Micropower Shunt Voltage Reference, 0.5% accuracy, 2.5 V, 15 ppm / degC, 15 mA, -40 to 125 degC, 3-pin SOT-23 (DBZ), Green (RoHS & no Sb/Br)"
U29 U32: library part CMP-0089785-1, "3V to 17V, 3A Micro Noise (20µVRMS) and Micro Ripple (200µVPP) buck converter"
U30 U31: library part CMP-0036365-5, "Single Output LDO, 1.5A, Adj. (0.8 to 3.6V), Programmable Soft-Start, DRC0010J (VSON-10)"
U33: library part CMP-0051392-2, "Single Buffer/Driver With Open-Drain Output, DCK0005A, SMALL T&R"
U34: library part CMP-0051904-4, "Dual Schmitt-Trigger Buffer, DSF0006A, LARGE T&R"
U35: library part CMP-0076016-2, "Level-Translating I2C Bus Repeater, DGK0008A (VSSOP-8)"
U36: library part CMP-0067107-3, "28V, 0.5A Step-Down Converter with SNOOZE Mode, DQC0010A (WSON-10)"
U38 U39 U40 U41: library part CMP-0073613-3, "4-Channel Ultra-Low-Capacitance IEC ESD Protection Diode, DQA0010A (USON-10)"
U42: library part CMP-0079884-2, "Automotive High Speed CAN Transceiver, DRB0008J (VSON-8)"
U43: library part CMP-0074359-2, "8-Bit Bidirectional Voltage-Level Shifter with Auto Direction Sensing and +/-15-kV ESD Protect, RGY0020A (VQFN-20)"
U45: library part CMP-0036402-3, "Single Output High PSRR LDO, 1 A, Adjustable 1.2 to 5.5 V Output, 2.7 to 5.5 V Input, 8-pin SON (DRB), -40 to 125 degC, Green (RoHS & no Sb/Br)"
U46: library part CMP-0051684-3, "Single Inverter, DCK0005A, LARGE T&R"
U48: library part CMP-0044782-1, "8-Bit LED Driver with I2C Interface, D0016A, TUBE"
U49 U51: library part CMP-0076540-1, "4-Bit One-of-2 FET Multiplexer/Demultiplexer 2.5-V/3.3-V Low-Voltage, High-Bandwidth Bus Switch, PW0016A (TSSOP-16)"
Y1 Y2 Y4: library part CMP-0084811-1, "Crystal, 25 MHz, 10 ppm, 4 pF, SMD"
Y3: library part CMP-0004635-3, "Crystal, 16 MHz, 8pF, SMD"
ZZ1: library part CMP-0003616-3
ZZ2: library part CMP-0077236-1
ZZ3: library part CMP-0077237-1
ZZ4: library part CMP-0077238-1

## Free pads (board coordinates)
  round 65.36 on Mech22: 1(-281.58,414) 1(249.42,53) 1(1196.42,275) 1(1203.42,-873) 1(1504.42,253) 1(2385.42,-444)
  round 15.62 on Mech22: 1(3783.19,-279.05)

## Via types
v1: diameter 18, hole 8, Top Layer to Bottom Layer, tented both sides, 1474 vias
v2: diameter 19.68, hole 7.87, Top Layer to Bottom Layer, tented both sides, 104 vias

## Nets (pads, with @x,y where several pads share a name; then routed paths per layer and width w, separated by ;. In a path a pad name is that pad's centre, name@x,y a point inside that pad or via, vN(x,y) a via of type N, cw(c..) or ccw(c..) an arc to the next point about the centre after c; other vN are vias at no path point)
ADC_EXT_VREF: J17.2 S2.3 S2.6 | length 299.9
  Bottom Layer w15: S2.6@1651.87,1121.1 S2.3@1797.54,1121.1 1797.54,1061.29 1760.02,1023.77 J17.2@1718.62,1023.77
AM263_ADC0_AIN0: C72.1 J1/J3.23 U1.V15 U12.1 U12.10 | length 3318.4
  Top Layer w4: 3988.08,815.87 U1.V15@3988.08,847.36
  Top Layer w5.3: v1(1775,548.33) C72.1@1745,548.33 1745,519.48 1753.65,510.82 1781.73,510.82 1795.63,496.93 U12.10@1795.63,480.91 U12.1@1795.63,448.04 1795.63,358.54 J1/J3.23@1804.17,350 ; 3988.08,815.87 3988.08,787.62 4017.81,757.88 4017.81,620.54 3992.7,595.43 3992.7,302.3 4025,270 v1(4025,240.62)
  SIG 1 w4.75: v1(1775,548.33) 1775,520 1844.48,450.52 3031.1,450.52 3099.1,382.52 3256.48,382.52 3318,321 3531.04,321 3626.14,225.9 3925.58,225.9 3940.3,240.62 v1(4025,240.62)
AM263_ADC0_AIN1: C82.1 J1/J3.28 U1.U15 U13.2 U13.9 | length 3004.4
  Top Layer w4: U1.U15@3988.08,878.86 4003.83,863.11 4003.83,815.87
  Top Layer w5.3: v1@2180,548.85 C82.1@2150,548.85 2150,516.35 2160.31,506.03 U13.9@2160.31,481.44 U13.2@2160.31,448.56 2160.31,421.62 2175,406.94 2247.24,406.94 J1/J3.28@2304.17,350 ; 4003.98,815.87 4003.98,794.2 4056.86,741.32 4056.86,498.59 4015,456.73 4015,323.76 v1(4050,288.76)
  SIG 1 w4.75: v1(2180,548.85) 2235.58,493.27 3066.73,493.27 3095.75,464.25 3263.62,464.25 3298,429.87 3298,400.5 3340.85,357.65 3599.47,357.65 3652.12,305 3721.32,305 3766.67,259.65 3993.32,259.65 4022.43,288.76 v1(4050,288.76)
AM263_ADC0_AIN2: U1.T14 U52.32 | length 790.2
  Top Layer w5.3: v1(4458.39,630.63) U52.32@4500.04,630.63
  Top Layer w10: U1.T14@3956.58,910.35 v1(3972.33,894.61)
  SIG 1 w4.75: v1(3972.33,894.61) 3972.33,885.08 3999.43,857.98 3999.43,762.5 4073.08,688.86 4305.29,688.86 4323.32,670.83 4381.38,670.83 4399.8,689.25 4465.75,689.25 4477.03,677.97 4477.03,649.27 v1(4458.39,630.63)
AM263_ADC0_AIN2_LIN1_TXD: C88.1 J5/J7.66 U14.5 U14.6 U52.7 | length 857.5
  Top Layer w5.3: J5/J7.66@4604.17,350 4635.87,350 4704.19,418.33 4842.8,418.33 4864.37,439.89 U14.5@4864.37,467.68 U14.6@4864.37,500.55 4864.37,516.12 4877.56,529.31 4902.1,529.31 4910,537.21 4910,560.42 C88.1@4911.11,561.53 4893.47,561.53 4885,570 4885,658.91 4861.58,682.33 4734.12,682.33 4682.42,630.63 U52.7@4629.96,630.63
AM263_ADC0_AIN3: C84.1 J1/J3.2 U1.U14 U13.5 U13.6 | length 3787.4
  Top Layer w4: U1.U14@3956.58,878.86 3972.4,863.04 3972.4,816.09 3972.18,815.87
  Top Layer w5.3: J1/J3.2@1704.17,250 1754.17,200 2325,200 2350,225 2350,282.66 2367.34,300 2434.55,300 2453.98,319.43 2453.98,386.33 2391.75,448.56 U13.5@2219.37,448.56 U13.6@2219.37,481.44 2219.37,494.53 2238.22,513.38 2261.62,513.38 2269,520.76 C84.1@2269,548.85 v1@2299,548.85 ; 3972.18,815.87 3972.18,780.46 3999.52,753.11 3999.52,624.73 3976.8,602.01 v1(3976.8,280)
  SIG 1 w4.75: v1(2299,548.85) 2334.35,513.5 3080.59,513.5 3115.59,478.5 3301.5,478.5 3319.1,460.9 3371.67,460.9 3395,437.57 3395,392.52 3415.02,372.5 3604.77,372.5 3658.02,319.25 3727.22,319.25 3766.47,280 v1(3976.8,280)
AM263_ADC0_AIN4: U1.U13
AM263_ADC0_AIN5: U1.R14
AM263_ADC1_AIN0: C73.1 J1/J3.24 U1.T11 U12.2 U12.9 | length 3552.9
  Top Layer w5.3: v1(1835,548.33) C73.1@1805,548.33 1805,515.82 1815.31,505.51 U12.9@1815.31,480.91 U12.2@1815.31,448.04 1815.31,405.72 1830,391.04 1863.14,391.04 J1/J3.24@1904.17,350
  Top Layer w10: U1.T11@3862.09,910.35 v1(3877.84,894.61)
  SIG 1 w4: v1(3877.84,894.61) 3875.16,891.93 3875.16,885.43 3875,885.26 3875,841.84 3885,831.84 3885,815.87
  SIG 1 w4.75: v1(1835,548.33) 1868.5,581.83 1994.64,581.83 2023.66,610.85 2520.85,610.85 2637.19,727.19 2731.8,727.19 2753.25,705.75 3030.87,705.75 3055,729.88 v1(3224.39,729.88) ; 3885,815.87 3885,569.25 3853.39,537.64 3844.74,537.64 3797.1,490 3749.68,490 3715.75,456.08 3715.75,431.53 3728.28,419 3793.51,419 3807.48,432.96 3870.67,432.96 3878.63,425 v1(3931.68,425)
  Bottom Layer w5.3: v1(3224.39,729.88) 3330.65,729.88 3395.48,665.06 3395.48,516.52 3454.23,457.77 3624.52,457.77 3655.64,426.64 3799.33,426.64 3843.06,470.38 3888.09,470.38 3931.68,426.78 v1(3931.68,425)
AM263_ADC1_AIN1: C83.1 J1/J3.29 U1.U11 U13.4 U13.7 | length 2751.7
  Top Layer w4: U1.U11@3862.09,878.86 3877.84,863.11 3877.84,837.51 3889.34,826 3889.34,815
  Top Layer w5.3: v1@2240,548.85 C83.1@2210,548.85 2210,515.31 2199.68,505 U13.7@2199.68,481.44 U13.4@2199.68,448.56 2199.68,428.15 2205,422.84 2331.34,422.84 J1/J3.29@2404.17,350 ; v1(3761.09,312.6) 3854.57,312.6 3909.82,367.86 3909.82,794.52 3889.34,815
  SIG 1 w4.75: v1(2240,548.85) 2259.25,568.1 2595.45,568.1 2635.8,527.75 3086.49,527.75 3121.49,492.75 3315.1,492.75 3332.7,475.15 3377.57,475.15 3413.27,439.45 3413.27,400.89 3426.5,387.66 3610.31,387.66 3664.47,333.5 3740.19,333.5 v1(3761.09,312.6)
AM263_ADC1_AIN2: U1.T12 U52.29 | length 993.2
  Top Layer w5.3: v1(4407.78,670) 4427.46,689.69 U52.29@4500.04,689.68
  Top Layer w10: U1.T12@3893.59,910.35 v1(3909.34,894.61)
  SIG 1 w4: 3890.46,850 3890.46,874.7 3909.34,893.58 v1(3909.34,894.61)
  SIG 1 w4.75: 3890.46,850 3904.9,835.56 3904.9,605 3949.9,560 4075.6,560 4140.36,624.76 4362.54,624.76 v1(4407.78,670)
AM263_ADC1_AIN2_SDFM0_D2: C92.1 J5/J7.67 U15.1 U15.10 U52.11 | length 926.3
  Top Layer w5.3: U52.11@4629.96,709.37 4897.79,709.37 4933.44,673.72 4933.44,574.11 4945.18,562.38 C92.1@4965,562.38 4965,540 4975,530 4988.59,530 4996.03,522.56 U15.10@4996.03,500.69 U15.1@4996.03,467.82 4996.03,440.53 4970.21,414.7 4865.21,414.7 4852.93,402.43 4756.6,402.43 J5/J7.67@4704.17,350
AM263_ADC1_AIN3: C97.1 D16.1 J1/J3.6 U1.V12 | length 3024.5
  Top Layer w4: U1.V12@3893.59,847.36 3905,835.95 3905,822.02 3911.16,815.87
  Top Layer w5.3: v1(2040,547.76) C97.1@2010,547.76 2010,485.62 D16.1@2010.51,485.1 2010.51,457.6 2028.08,440.03 2082.25,440.03 2151,371.28 2151,296.83 J1/J3.6@2104.17,250 ; v1(3668.01,260.08) 3681.78,246.32 3734.94,246.32 3783.62,295 3873.41,295 3951.58,373.17 3951.58,775.44 3911.16,815.87
  SIG 1 w4.75: v1(2040,547.76) 2122.99,464.77 3037,464.77 3105,396.77 3260.73,396.77 3325.5,332 3544.5,332 3616.42,260.08 v1(3668.01,260.08)
AM263_ADC1_AIN4: U1.U12
AM263_ADC1_AIN5: U1.R12
AM263_ADC2_AIN0: C74.1 J1/J3.25 U1.R10 U12.4 U12.7 | length 3359.5
  Top Layer w5.3: v1(1895,548.33) C74.1@1865,548.33 1865,514.79 1854.68,504.48 U12.7@1854.68,480.91 U12.4@1854.68,448.04 1854.68,422.25 1870,406.94 1947.24,406.94 J1/J3.25@2004.17,350
  Top Layer w10: U1.R10@3830.6,941.85 v1(3846.35,926.1)
  SIG 1 w4.75: v1(1895,548.33) 1914.25,567.58 2001,567.58 2030.03,596.6 2556.61,596.6 2601.75,641.74 2733.26,641.74 2776.52,685 3031.05,685 3060.94,714.89 3113.33,714.89 3129.56,698.66 v1(3275,698.66) ; v1(3835,363.27) 3807.77,390.5 3708.44,390.5 3682.23,416.7 3682.23,464.48 3783.89,566.14 3796.1,566.14 3832.75,602.79 3832.75,778.4 3815,796.15 3815,894.76 v1(3846.35,926.1)
  Bottom Layer w5.3: v1(3275,698.66) 3313.45,660.21 3313.45,543 3414.59,441.87 3448.13,441.87 3494,396 3802.27,396 v1(3835,363.27)
AM263_ADC2_AIN1: U1.T10 U52.38 | length 1470.1
  Top Layer w5.3: v1(4458.39,512.52) U52.38@4500.04,512.52
  Top Layer w10: U1.T10@3830.6,910.35 v1(3846.35,894.61)
  SIG 1 w4: v1(3846.35,894.61) 3847,893.95 3847,815.87
  SIG 1 w4.75: 3847,815.87 3847,799.35 3870.75,775.6 3870.75,579.71 3842.93,551.89 3791.41,551.89 3700.43,460.9 3700.43,426.71 3722.38,404.75 3825.52,404.75 3844.52,385.75 3955.25,385.75 4047.73,478.24 4343.24,478.24 4352.03,487.03 4432.9,487.03 v1(4458.39,512.52)
AM263_ADC2_AIN1_MCAN1_RX: C85.1 J5/J7.63 U14.1 U14.10 U52.4 | length 772.8
  Top Layer w5.3: J5/J7.63@4304.17,350 4374.17,420 4650.72,420 4698.4,467.68 U14.1@4785.63,467.68 U14.10@4785.63,500.55 4785.63,519.99 4774.59,531.03 4755.01,531.03 4747.11,538.93 C85.1@4747.11,561.53 4715.63,561.53 4705.59,571.57 U52.4@4629.96,571.57
AM263_ADC2_AIN2: U1.U10 U52.27 | length 1481.7
  Top Layer w5.3: U1.U10@3830.6,878.86 3813.63,861.89 3813.63,832.56 3785,803.94 3785,590 3880,495 v1(3880,450.85) ; v1(4417.1,713.38) 4432.77,729.06 U52.27@4500.04,729.06
  SIG 1 w4.75: v1(3880,450.85) 3921.63,492.49 4317.74,492.49 4357.02,531.77 4477.64,531.77 4495.75,549.88 4495.75,703.31 4470,729.06 4432.77,729.06 v1(4417.1,713.38)
AM263_ADC2_AIN2_SDFM0_CLK2: C93.1 J5/J7.68 U15.2 U15.9 U52.12 | length 879.5
  Top Layer w5.3: U52.12@4629.96,729.06 4909.46,729.06 4990,648.51 4990,570 4998.33,561.67 C93.1@5017.97,561.67 5015.48,559.18 5015.48,500.94 U15.9@5015.72,500.69 U15.2@5015.72,467.82 5015.72,432.26 4983.46,400 4879.37,400 4829.37,350 J5/J7.68@4804.17,350
AM263_ADC2_AIN3: C95.1 J5/J7.42 U1.T9 U15.5 U15.6 | length 3539.7
  Top Layer w5.3: J5/J7.42@4204.17,250 4280.97,173.2 4801.74,173.2 4852.06,223.52 4852.06,265 4880.13,293.06 5039.39,293.06 5074.77,328.45 U15.5@5074.77,467.82 ; v1(5160,561.03) 5159.36,561.67 C95.1@5128.54,561.67 5128.54,542.46 5114.41,528.33 5085.81,528.33 5074.77,517.29 U15.6@5074.77,500.69 ; U15.5@5074.77,467.82 U15.6@5074.77,500.69 ; U15.5@5074.77,467.82 U15.6@5074.77,500.69
  Top Layer w10: v1(3783.35,894.61) U1.T9@3799.1,910.35
  SIG 1 w4.75: v1(3783.35,894.61) 3794.9,883.06 3794.9,754.51 3785,744.61 3785,587.4 3665.68,468.08 3665.68,406.97 3696.4,376.25 3781.88,376.25 3823.5,334.63 3971.9,334.63 4077.01,439.74 4132.97,439.74 4157.22,463.99 4287.17,463.99 4318,433.16 4393.5,433.16 4431.09,470.75 5069.72,470.75 v1(5160,561.03)
AM263_ADC2_AIN4: U1.V9
AM263_ADC2_AIN5: U1.T8
AM263_ADC3_AIN0: C75.1 J1/J3.26 U1.U7 U12.5 U12.6 | length 2730.5
  Top Layer w5.3: v1(1954,548.33) C75.1@1924,548.33 1924,520.24 1916.62,512.86 1887.02,512.86 1874.37,500.2 U12.6@1874.37,480.91 U12.5@1874.37,448.04 1874.37,428.47 1880,422.84 2031.34,422.84 J1/J3.26@2104.17,350
  Top Layer w10: v1(3720.36,863.11) U1.U7@3736.11,878.86
  SIG 1 w4: v1@3720.36,862.49 v1(3720.36,863.11)
  SIG 1 w4.75: v1(1954,548.33) 2007.95,548.33 2041.97,582.35 2570,582.35 2615.14,627.49 2739.16,627.49 2771.67,660 3053.54,660 3163.53,550.01 3304.97,550.01 3350.45,504.53 3389.28,504.53 3441.06,452.75 3589.89,452.75 3741.83,604.69 3741.83,786.42 3751.48,796.07 3751.48,831.37 v1@3720.36,862.49
AM263_ADC3_AIN1: U1.U8 U52.36 | length 1226.9
  Top Layer w5.3: U1.U8@3767.61,878.86 3782.13,864.33 3782.13,829.46 3769.58,816.91 3769.58,458.43 v1(3781.85,446.17) ; v1(4458.39,551.89) U52.36@4500.04,551.89
  SIG 1 w4.75: v1(3781.85,446.17) 3788.43,452.75 3854.68,452.75 3908.66,506.74 4306.74,506.74 4371.14,571.14 4439.14,571.14 v1(4458.39,551.89)
AM263_ADC3_AIN1_MCAN1_TX: C86.1 J5/J7.64 U14.2 U14.9 U52.5 | length 812.1
  Top Layer w5.3: J5/J7.64@4404.17,350 4462.03,407.86 4653.57,407.86 4690.71,445 4799.14,445 4805.31,451.17 U14.2@4805.31,467.68 U14.9@4805.31,500.55 4805.31,533.2 4802.11,536.4 C86.1@4802.11,561.53 4780.42,561.53 4772.38,569.58 4772.38,630 4765.84,636.54 4719.02,636.54 4673.74,591.26 U52.5@4629.96,591.26
AM263_ADC3_AIN2: U1.T7 U52.25 | length 1796
  Top Layer w5.3: v1(4220,419.26) 4231.5,430.75 4231.5,611.09 4300.41,680 4326.38,680 4359.76,713.38 4367,713.38 4422.04,768.43 U52.25@4500.04,768.43
  Top Layer w10: v1(3720.36,894.61) U1.T7@3736.11,910.35
  SIG 1 w4.75: v1(3720.36,894.61) 3720.36,893.05 3765.73,847.67 3765.73,776.62 3756.08,766.97 3756.08,598.79 3634.18,476.89 3634.18,393.18 3679.62,347.75 3770.07,347.75 3811.7,306.13 3989.63,306.13 4094.74,411.24 4211.98,411.24 v1(4220,419.26)
AM263_ADC3_AIN2_SDFM0_D3: C94.1 J5/J7.69 U15.4 U15.7 U52.13 | length 984.4
  Top Layer w5.3: U52.13@4629.96,748.74 4948.18,748.74 5040.31,656.61 5040.31,573.23 5051.87,561.67 C94.1@5073,561.67 5073,538 5055.09,520.09 U15.7@5055.09,500.69 U15.4@5055.09,467.82 5055.09,331.25 5032.8,308.96 4945.21,308.96 J5/J7.69@4904.17,350
AM263_ADC3_AIN3: C96.1 D15.2 J5/J7.46 U1.R7 | length 2133.9
  Top Layer w5.3: v1(4300.31,423.62) 4300.31,508.74 4317.89,526.31 C96.1@4339.72,526.31 4339.72,467.6 D15.2@4338.78,466.66 4338.78,423.78 4310,395 4282.16,395 4257.41,370.25 4257.41,329.77 4284.26,302.93 4551.24,302.93 J5/J7.46@4604.17,250
  Top Layer w10: v1(3720.36,926.1) U1.R7@3736.11,941.85
  SIG 1 w4: v1(3720.36,926.1) 3736.86,909.61 3736.86,888.39 3779.98,845.27
  SIG 1 w4.75: 3779.98,845.27 3779.98,764.98 3770.33,755.33 3770.33,592.89 3650,472.55 3650,397.52 3685.52,362 3775.98,362 3817.6,320.38 3983.73,320.38 4088.84,425.49 4138.88,425.49 4162.23,448.84 4275.09,448.84 v1(4300.31,423.62)
AM263_ADC3_AIN4: U1.V8
AM263_ADC3_AIN5: U1.U9
AM263_ADC4_AIN0: C81.1 J1/J3.27 U1.U6 U13.1 U13.10 | length 2712.5
  Top Layer w5.3: v1@2120,548.85 C81.1@2090,548.85 2090,520 2098.65,511.35 2124.65,511.35 2140.63,495.36 U13.10@2140.63,481.44 U13.1@2140.63,448.56 2140.63,413.54 J1/J3.27@2204.17,350 ; v1(3694.17,285) 3755.86,346.68 3755.86,466.58 3722.44,500 3690,500 3628.99,561.01 3628.99,727.74 3687.64,786.39 3687.64,861.89 U1.U6@3704.61,878.86
  SIG 1 w4.75: v1(2120,548.85) 2120,522.52 2163.5,479.02 3050.98,479.02 3118.98,411.02 3267.48,411.02 3334,344.5 3555,344.5 3614.5,285 v1(3694.17,285)
AM263_ADC4_AIN1: U1.V5 U52.34 | length 1326.7
  Top Layer w5.3: U1.V5@3673.12,847.36 3673.12,797.41 3613.09,737.38 3613.09,549.79 3714.78,448.1 v1(3735,448.1) ; v1(4458.39,591.26) U52.34@4500.04,591.26
  SIG 1 w4.75: v1(3735,448.1) 3758.61,471.71 3853.48,471.71 3906.06,524.29 4295.27,524.29 4381.49,610.51 4439.14,610.51 v1(4458.39,591.26)
AM263_ADC4_AIN1_LIN1_RXD: C87.1 J5/J7.65 U14.4 U14.7 U52.6 | length 837
  Top Layer w5.3: J5/J7.65@4504.17,350 4551.43,397.26 4662,397.26 4696.12,431.38 4826.04,431.38 4844.69,450.03 U14.4@4844.69,467.68 U14.7@4844.69,500.55 4844.69,527.99 4856.7,540 C87.1@4856.7,561.53 4838.47,561.53 4827.2,572.8 4827.2,651.1 4812.48,665.82 4732.61,665.82 4677.73,610.94 U52.6@4629.96,610.94
AM263_ADC4_AIN2: U1.V4
AM263_ADC4_AIN3: U1.U5
AM263_ADC4_AIN4: U1.V3
AM263_ADC4_AIN5: U1.U4
AM263_ADC_CAL0: U1.U16
AM263_ADC_CAL1: U1.T15
AM263_ADC_VREFHI_G01: C77.1 C79.1 C80.1 S2.2 U1.V10 U1.V14 | length 5924.9
  Top Layer w15: U1.V10@3830.6,847.36 3831.11,846.85 v1(3831.11,816.77) 3831.11,810.33 3830.6,809.82 3855,785.41 C77.1@3855,758.87 ; v1(3956.58,825) U1.V14@3956.58,847.36
  SIG 1 w15: v1(1881.26,1079.09) 1892.09,1068.26 1892.09,905.2 1964.73,832.57 1964.73,674.26 1944.82,654.35 1790.45,654.35 1770,633.9 1770,596.59 1533.7,360.28 1533.7,144.46 1604.73,73.43 2068.73,73.43 2099.68,104.37 2723.63,104.37 2733.12,94.88 2860.51,94.88 3060.41,294.78 3250,294.78 3316.5,228.28 3316.5,123.5 3344.87,95.13 3520.66,95.13 3550.31,124.78 3678.51,124.78 3716.07,87.22 3822.14,87.22 3859.35,50 4149.88,50 4254.88,155 v1(4255,155) ; v1(3956.58,825) 3956.01,824.43 3956.01,822.3 3955.63,821.92 3955.63,719.49 3956.05,719.06 3956.05,716.42 4035.38,637.09 4101.11,637.09 4115.3,651.28 v1(4311.54,651.28)
  Bottom Layer w15: S2.2@1797.54,1190 1839.19,1190 1881.26,1147.93 v1(1881.26,1079.09) ; v1(3831.11,816.77) 3823.14,808.8 3823.14,769.23 3829.62,762.75 3958.56,762.75 3972.24,776.43 C80.1@3972.24,789.94 3972.24,809.34 v1(3956.58,825) ; v1(4255,155) 4255,365.72 4285.17,395.89 4307.05,395.89 4329.69,418.53 4329.69,601.57 4311.54,619.71 v1(4311.54,651.28)
AM263_ADC_VREFHI_G2: C76.1 C78.1 S2.5 U1.V6 | length 3381
  Top Layer w15: U1.V6@3704.61,847.36 v1(3704.61,825) 3704.61,742.32 3713.32,733.62 3713.32,698.14 C76.1@3713.17,698
  SIG 1 w8: 3704.49,800.8 3707.05,798.24 ; v1@3704.49,824.87 v1(3704.61,825)
  SIG 1 w20: v1(1935,940) 1935,912.11 1998.13,848.98 1998.13,680.65 2018.77,660 2234.9,660 2342.91,768.02 2602.89,768.02 2620.91,750 2739.93,750 2759.93,730 2979.51,730 3008.2,758.68 3210.94,758.68 3230.34,778.09 3401.52,778.09 3444.13,735.48 3444.13,622.47 3504.51,562.09 3504.51,552.94 3520.25,537.2 3550.76,537.2 3650.66,637.09 3700.33,637.09 3715.62,652.38 3715.62,789.67 3707.05,798.24 ; 3704.49,800.8 v1@3704.49,824.87
  Bottom Layer w15: S2.5@1651.87,1190 1697.96,1190 1721.8,1213.85 1721.8,1286.8 1767.62,1332.62 1805,1332.62 1890.03,1247.59 1890.03,1174.7 1910,1154.73 1910,965 v1(1935,940) ; C78.1@3696.74,789.94 3696.74,817.13 v1(3704.61,825)
AM263_ADC_VREFLO_G01: C77.2 C79.2 C80.2 R44.2 U1.V11 U1.V13 | length 413.8
  Top Layer w4: v1(3925.09,825) U1.V13@3925.09,847.36
  Top Layer w15: U1.V11@3862.09,847.36 v1(3862.09,825) 3862.67,824.43 3862.67,812.33 3889.07,785.92 3889.07,707.15 3877.8,695.88 C77.2@3855,695.88 3855,666.5 3872.63,648.88 R44.2@3872.63,631.2
  Bottom Layer w15: v1(3862.09,825) 3862.09,824.19 3868.43,817.85 C79.2@3868.43,789.94 C80.2@3925,789.94 3925,824.91 v1(3925.09,825)
AM263_ADC_VREFLO_G2: C76.2 C78.2 R307.2 U1.V7 | length 362.5
  Top Layer w15: R307.2@3713.62,555 3713.17,555.45 C76.2@3713.17,635.01 3737.59,635.01 3748.83,646.26 3748.83,733.91 3736.11,746.64 v1@3736.11,822.29 ; v1(3736.11,825) U1.V7@3736.11,847.36
  Bottom Layer w15: v1(3736.11,825) 3743.98,817.13 C78.2@3743.98,789.94
AM263_ATESTV0: U1.U3
AM263_ATESTV1: U1.V2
